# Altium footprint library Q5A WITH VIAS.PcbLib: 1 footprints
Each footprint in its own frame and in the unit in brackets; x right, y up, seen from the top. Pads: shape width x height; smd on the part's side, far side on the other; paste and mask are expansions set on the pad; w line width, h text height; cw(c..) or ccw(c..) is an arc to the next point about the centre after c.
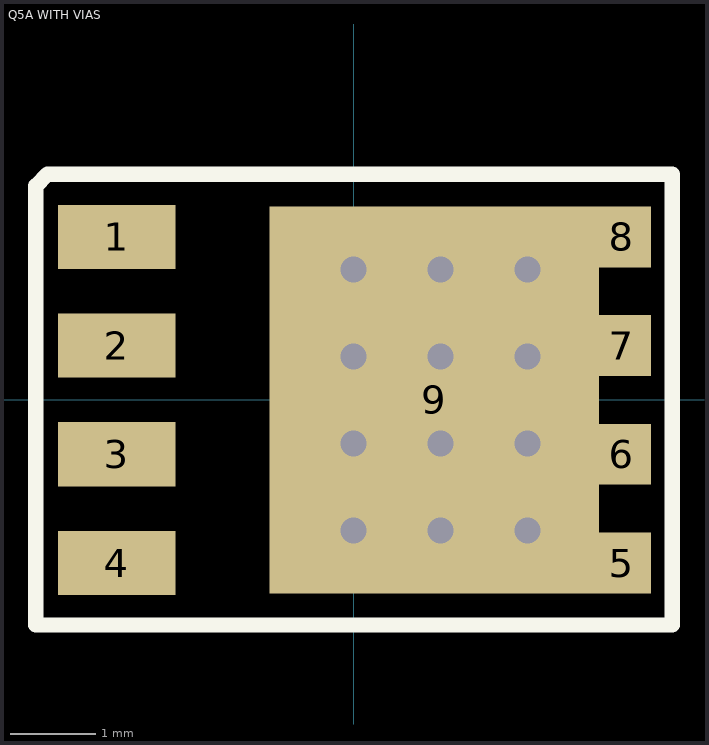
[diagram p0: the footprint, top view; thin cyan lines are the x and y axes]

## Q5A WITH VIAS [mm] "TI 15A WITH VIAS"
height 1.1
pads (10):
  round 0.3 on Top Overlay: 0(-2.766,3.087)
  rect 1.372x0.75 smd paste-0.1 mask+0.051: 1(-2.77,1.905) 2(-2.77,0.635) 3(-2.77,-0.635) 4(-2.77,-1.905)
  rect 0.675x0.71 smd paste-0.1 mask+0.051: 5(3.134,-1.905) 6(3.134,-0.635) 7(3.134,0.635) 8(3.134,1.905)
  rect 3.85x4.52 smd paste-2.2 mask+0.051: 9(0.939,0)
via 2.032,-1.524 diameter 0.61 hole 0.305
via 2.032,-0.508 diameter 0.61 hole 0.305
via 2.032,0.508 diameter 0.61 hole 0.305
via 2.032,1.524 diameter 0.61 hole 0.305
via 1.016,-1.524 diameter 0.61 hole 0.305
via 1.016,-0.508 diameter 0.61 hole 0.305
via 1.016,0.508 diameter 0.61 hole 0.305
via 1.016,1.524 diameter 0.61 hole 0.305
via 0,-1.524 diameter 0.61 hole 0.305
via 0,-0.508 diameter 0.61 hole 0.305
via 0,0.508 diameter 0.61 hole 0.305
via 0,1.524 diameter 0.61 hole 0.305
Top Overlay:
  lines w0.178: -3.713,-2.63 0.165,-2.63 3.721,-2.63 3.721,0.321 3.721,2.638 0.157,2.638 -3.577,2.638 -3.713,2.502 -3.713,0.935 -3.713,-2.63
Top Paste:
  region: 0.323,0.31 0.323,1.88 1.908,1.88 1.908,0.31
  region: 0.323,-0.31 0.323,-1.88 1.908,-1.88 1.908,-0.31
M5 Assembly Top:
  text ".Designator" at 0.004,-0.005 h1.02
3D body: height 1.11, standoff 0, extent -3.05,-2.5 3.05,2.5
